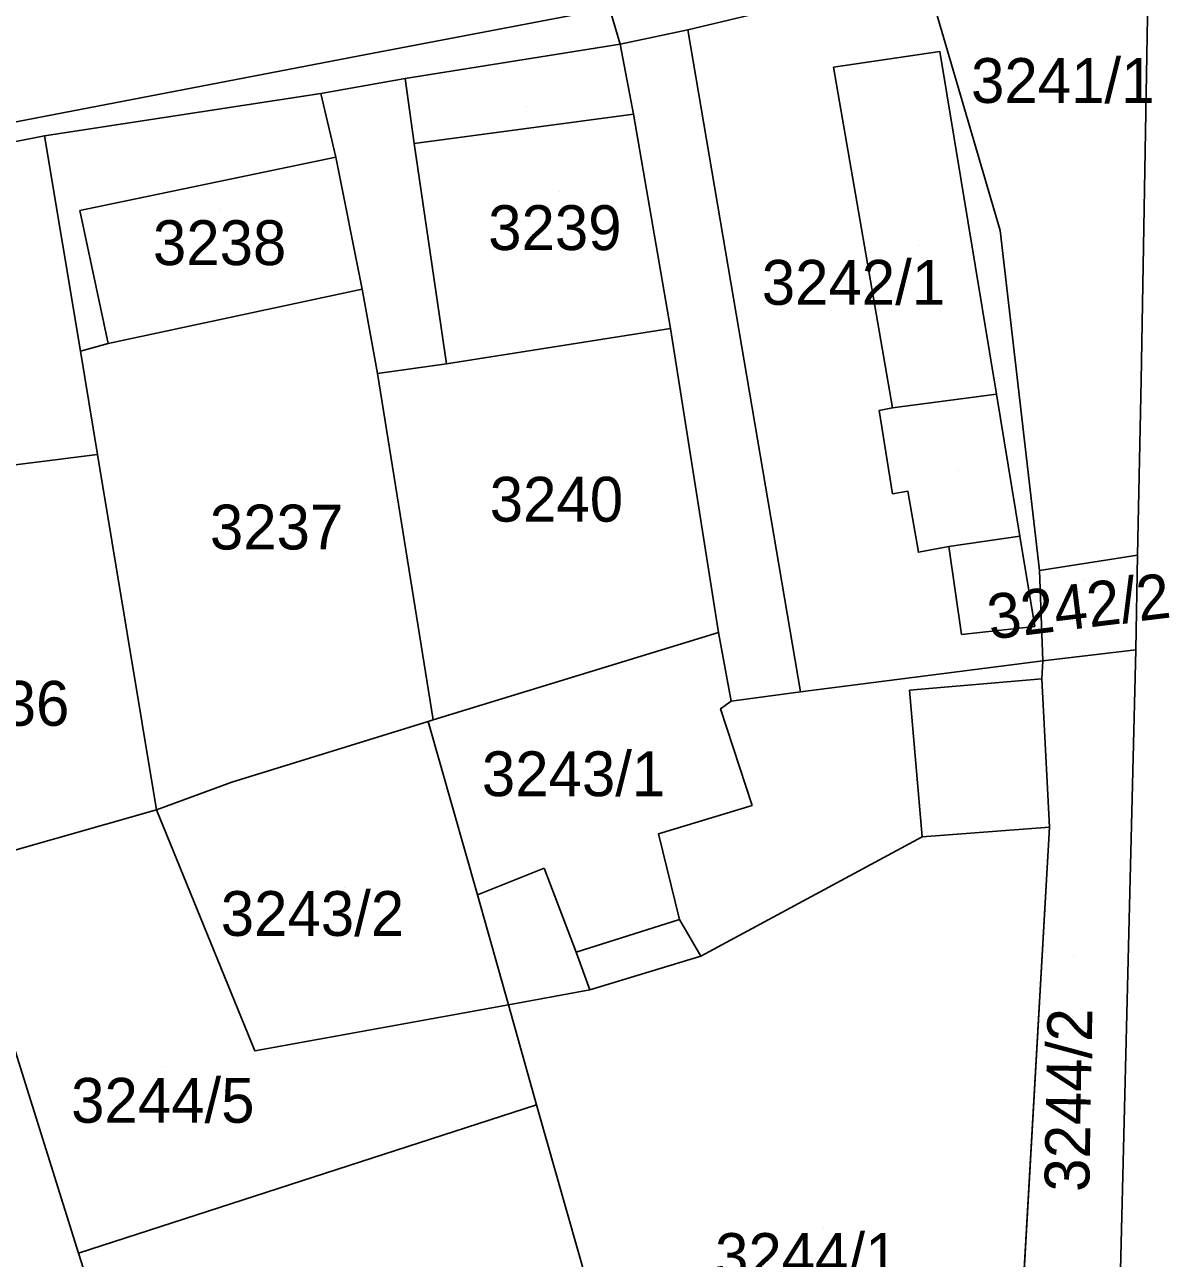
# Model space of a CAD drawing. Extents: x -262657 to -261595, y -1238015 to -1237156.
# Drawn here: x -261855.8 to -261804.7, y -1237748.7 to -1237693.7 of the extents above; entities that cross this region are included whole.
import ezdxf

# ---------------------------------------------------------------- set-up
doc = ezdxf.new("R2010")
doc.units = 0
for name, color, linetype in [('body_kn', 7, 'Continuous'), ('kladpar_druhypozemkov', 7, 'Continuous'), ('kladpar_hranice', 7, 'Continuous'), ('kladpar_parcelnecisla', 7, 'Continuous'), ('kladpar_plochy', 7, 'Continuous'), ('tarchy_linie', 7, 'Continuous'), ('zappar_hrandruhpozemk', 7, 'Continuous')]:
    doc.layers.add(name, color=color, linetype=linetype)

msp = doc.modelspace()

# ---------------------------------------------------------------- linework, layer by layer
at = {"layer": 'body_kn'}
for p, q in [((-261826.22, -1237693.91), (-261826.22, -1237693.91)), ((-261826.22, -1237693.91), (-261826.22, -1237693.91)), ((-261829.24, -1237694.55), (-261829.24, -1237694.55)), ((-261829.24, -1237694.55), (-261829.24, -1237694.55)), ((-261814.99, -1237694.87), (-261814.99, -1237694.87)), ((-261840.58, -1237695.01), (-261840.58, -1237695.01)), ((-261819.73, -1237695.57), (-261819.73, -1237695.57)), ((-261819.73, -1237695.57), (-261819.73, -1237695.57)), ((-261838.83, -1237696.08), (-261838.83, -1237696.08)), ((-261842.59, -1237696.75), (-261842.59, -1237696.75)), ((-261842.59, -1237696.75), (-261842.59, -1237696.75)), ((-261828.65, -1237697.67), (-261828.65, -1237697.67)), ((-261828.65, -1237697.67), (-261828.65, -1237697.67)), ((-261854.92, -1237698.64), (-261854.92, -1237698.64)), ((-261854.92, -1237698.64), (-261854.92, -1237698.64)), ((-261838.43, -1237698.98), (-261838.43, -1237698.98)), ((-261838.43, -1237698.98), (-261838.43, -1237698.98)), ((-261841.92, -1237699.59), (-261841.92, -1237699.59)), ((-261805.84, -1237700.16), (-261805.84, -1237700.16)), ((-261853.35, -1237701.96), (-261853.35, -1237701.96)), ((-261812.29, -1237702.86), (-261812.29, -1237702.86)), ((-261840.75, -1237705.47), (-261840.75, -1237705.47)), ((-261827, -1237707.23), (-261827, -1237707.23)), ((-261852.08, -1237707.9), (-261852.08, -1237707.9)), ((-261852.08, -1237707.9), (-261852.08, -1237707.9)), ((-261853.32, -1237708.24), (-261853.32, -1237708.24)), ((-261840.06, -1237709.24), (-261840.06, -1237709.24)), ((-261836.99, -1237708.8), (-261836.99, -1237708.8)), ((-261806, -1237709.55), (-261806, -1237709.55)), ((-261812.46, -1237710.15), (-261812.46, -1237710.15)), ((-261817.69, -1237710.88), (-261817.69, -1237710.88)), ((-261817.09, -1237710.76), (-261817.09, -1237710.76)), ((-261817.09, -1237710.76), (-261817.09, -1237710.76)), ((-261852.56, -1237712.85), (-261852.56, -1237712.85)), ((-261817.09, -1237714.6), (-261817.09, -1237714.6)), ((-261816.41, -1237714.48), (-261816.41, -1237714.48)), ((-261814.58, -1237716.95), (-261814.58, -1237716.95)), ((-261814.58, -1237716.95), (-261814.58, -1237716.95)), ((-261811.41, -1237716.49), (-261811.41, -1237716.49)), ((-261815.94, -1237717.2), (-261815.94, -1237717.2)), ((-261806.16, -1237717.33), (-261806.16, -1237717.33)), ((-261810.54, -1237718.01), (-261810.54, -1237718.01)), ((-261824.85, -1237720.78), (-261824.85, -1237720.78)), ((-261810.75, -1237720.51), (-261810.75, -1237720.51)), ((-261814.01, -1237720.87), (-261814.01, -1237720.87)), ((-261806.24, -1237721.56), (-261806.24, -1237721.56)), ((-261810.39, -1237722.04), (-261810.39, -1237722.04)), ((-261810.39, -1237722.04), (-261810.39, -1237722.04)), ((-261810.43, -1237722.85), (-261810.43, -1237722.85)), ((-261810.43, -1237722.85), (-261810.43, -1237722.85)), ((-261821.2, -1237723.42), (-261821.2, -1237723.42)), ((-261816.34, -1237723.35), (-261816.34, -1237723.35)), ((-261824.29, -1237723.84), (-261824.29, -1237723.84)), ((-261824.76, -1237724.18), (-261824.76, -1237724.18)), ((-261837.8, -1237724.75), (-261837.8, -1237724.75)), ((-261837.8, -1237724.75), (-261837.8, -1237724.75)), ((-261837.58, -1237724.68), (-261837.58, -1237724.68)), ((-261837.58, -1237724.68), (-261837.58, -1237724.68)), ((-261846.57, -1237727.46), (-261846.57, -1237727.46)), ((-261823.36, -1237728.5), (-261823.36, -1237728.5)), ((-261849.93, -1237728.69), (-261849.93, -1237728.69)), ((-261849.93, -1237728.69), (-261849.93, -1237728.69)), ((-261810.09, -1237729.46), (-261810.09, -1237729.46)), ((-261810.09, -1237729.46), (-261810.09, -1237729.46)), ((-261827.54, -1237729.76), (-261827.54, -1237729.76)), ((-261815.77, -1237729.89), (-261815.77, -1237729.89)), ((-261832.64, -1237731.29), (-261832.64, -1237731.29)), ((-261835.61, -1237732.48), (-261835.61, -1237732.48)), ((-261835.61, -1237732.48), (-261835.61, -1237732.48)), ((-261826.6, -1237733.58), (-261826.6, -1237733.58)), ((-261831.21, -1237735.03), (-261831.21, -1237735.03)), ((-261825.65, -1237735.22), (-261825.65, -1237735.22)), ((-261830.6, -1237736.72), (-261830.6, -1237736.72)), ((-261834.22, -1237737.38), (-261834.22, -1237737.38)), ((-261845.54, -1237739.43), (-261845.54, -1237739.43)), ((-261832.97, -1237741.84), (-261832.97, -1237741.84)), ((-261853.4, -1237748.46), (-261853.4, -1237748.46))]:
    msp.add_line(p, q, dxfattribs=at)
at = {"layer": 'kladpar_druhypozemkov'}
for p, q in [((-261809.96, -1237695.1), (-261809.96, -1237695.1)), ((-261833.43, -1237697.34), (-261833.43, -1237697.34)), ((-261831.97, -1237701.13), (-261831.97, -1237701.13)), ((-261847.09, -1237701.92), (-261847.09, -1237701.92)), ((-261815.9, -1237703.54), (-261815.9, -1237703.54)), ((-261814.16, -1237713.57), (-261814.16, -1237713.57)), ((-261831.97, -1237714.18), (-261831.97, -1237714.18)), ((-261844.26, -1237715.4), (-261844.26, -1237715.4)), ((-261808.53, -1237718.42), (-261808.53, -1237718.42)), ((-261830.66, -1237726.42), (-261830.66, -1237726.42)), ((-261841.56, -1237732.14), (-261841.56, -1237732.14)), ((-261809.02, -1237735.2), (-261809.02, -1237735.2)), ((-261849.54, -1237740.13), (-261849.54, -1237740.13)), ((-261820.16, -1237747.37), (-261820.16, -1237747.37))]:
    msp.add_line(p, q, dxfattribs=at)
at = {"layer": 'kladpar_hranice'}
for p, q in [((-261811.6, -1237755.76), (-261810.09, -1237729.46)), ((-261810.09, -1237729.46), (-261811.6, -1237755.76))]:
    msp.add_line(p, q, dxfattribs=at)
for points in [[(-261806.69, -1237689.75), (-261806.16, -1237692.56), (-261805.71, -1237692.47), (-261805.84, -1237700.16), (-261806, -1237709.55), (-261806.16, -1237717.33), (-261810.54, -1237718.01), (-261812.29, -1237702.86), (-261815.65, -1237691.39), (-261812.47, -1237690.82), (-261810.26, -1237690.45), (-261806.69, -1237689.75)], [(-261815.65, -1237691.39), (-261826.22, -1237693.91), (-261829.24, -1237694.55), (-261838.83, -1237696.08), (-261842.59, -1237696.75), (-261854.92, -1237698.64), (-261868.9, -1237701.4), (-261879, -1237704.16), (-261885.26, -1237705.39), (-261886.66, -1237705.67), (-261889.62, -1237706.2), (-261900.57, -1237708.21)], [(-261829.24, -1237694.55), (-261826.22, -1237693.91), (-261815.65, -1237691.39), (-261812.29, -1237702.86), (-261810.54, -1237718.01), (-261810.39, -1237722.04), (-261821.2, -1237723.42), (-261824.29, -1237723.84), (-261824.85, -1237720.78), (-261827, -1237707.23), (-261828.65, -1237697.67), (-261829.24, -1237694.55)], [(-261842.59, -1237696.75), (-261838.83, -1237696.08), (-261829.24, -1237694.55), (-261828.65, -1237697.67), (-261827, -1237707.23), (-261836.99, -1237708.8), (-261840.06, -1237709.24), (-261840.75, -1237705.47), (-261841.92, -1237699.59), (-261842.59, -1237696.75)], [(-261854.92, -1237698.64), (-261842.59, -1237696.75), (-261841.92, -1237699.59), (-261840.75, -1237705.47), (-261852.08, -1237707.9), (-261853.32, -1237708.24), (-261854.92, -1237698.64)], [(-261868.9, -1237701.4), (-261854.92, -1237698.64), (-261853.32, -1237708.24), (-261852.56, -1237712.85), (-261864.53, -1237714.35), (-261868.9, -1237701.4)], [(-261837.58, -1237724.68), (-261837.8, -1237724.75), (-261846.57, -1237727.46), (-261849.93, -1237728.69), (-261852.56, -1237712.85), (-261853.32, -1237708.24), (-261852.08, -1237707.9), (-261840.75, -1237705.47), (-261840.06, -1237709.24), (-261837.58, -1237724.68)], [(-261837.58, -1237724.68), (-261840.06, -1237709.24), (-261836.99, -1237708.8), (-261827, -1237707.23), (-261824.85, -1237720.78), (-261837.58, -1237724.68)], [(-261858.82, -1237731.22), (-261861.09, -1237724.45), (-261861.86, -1237722.15), (-261862.57, -1237720.05), (-261864.53, -1237714.35), (-261852.56, -1237712.85), (-261849.93, -1237728.69), (-261858.82, -1237731.22)], [(-261810.39, -1237722.04), (-261810.54, -1237718.01), (-261806.16, -1237717.33), (-261806.24, -1237721.56), (-261810.39, -1237722.04)], [(-261837.8, -1237724.75), (-261837.58, -1237724.68), (-261824.85, -1237720.78), (-261824.29, -1237723.84), (-261821.2, -1237723.42), (-261810.39, -1237722.04), (-261810.43, -1237722.85), (-261810.09, -1237729.46), (-261815.77, -1237729.89), (-261825.65, -1237735.22), (-261830.6, -1237736.72), (-261834.22, -1237737.38), (-261835.61, -1237732.48), (-261837.8, -1237724.75)], [(-261810.39, -1237722.04), (-261806.24, -1237721.56), (-261807.05, -1237754.01), (-261811.6, -1237755.76)], [(-261810.09, -1237729.46), (-261810.43, -1237722.85), (-261810.39, -1237722.04)], [(-261849.93, -1237728.69), (-261846.57, -1237727.46), (-261837.8, -1237724.75), (-261835.61, -1237732.48), (-261834.22, -1237737.38), (-261845.54, -1237739.43), (-261849.93, -1237728.69)], [(-261849.93, -1237728.69), (-261845.54, -1237739.43), (-261834.22, -1237737.38), (-261832.97, -1237741.84), (-261853.4, -1237748.46), (-261858.82, -1237731.22), (-261849.93, -1237728.69)], [(-261811.6, -1237755.76), (-261860.68, -1237774.55), (-261869.5, -1237752.69), (-261870.26, -1237752.98), (-261874.12, -1237742.17), (-261876.61, -1237737.16), (-261872.44, -1237735.73), (-261868.9, -1237734.59), (-261864.8, -1237732.66), (-261858.82, -1237731.22), (-261853.4, -1237748.46), (-261848.36, -1237764.27), (-261828.48, -1237757.63), (-261832.97, -1237741.84), (-261834.22, -1237737.38), (-261830.6, -1237736.72), (-261825.65, -1237735.22), (-261815.77, -1237729.89), (-261810.09, -1237729.46)], [(-261848.36, -1237764.27), (-261853.4, -1237748.46), (-261832.97, -1237741.84), (-261828.48, -1237757.63), (-261848.36, -1237764.27)]]:
    msp.add_lwpolyline(points, dxfattribs=at)
at = {"layer": 'kladpar_plochy'}
for points in [[(-261806.69, -1237689.75), (-261806.16, -1237692.56), (-261805.71, -1237692.47), (-261805.84, -1237700.16), (-261806, -1237709.55), (-261806.16, -1237717.33), (-261810.54, -1237718.01), (-261812.29, -1237702.86), (-261815.65, -1237691.39), (-261812.47, -1237690.82), (-261810.26, -1237690.45)], [(-261829.24, -1237694.55), (-261826.22, -1237693.91), (-261815.65, -1237691.39), (-261812.29, -1237702.86), (-261810.54, -1237718.01), (-261810.39, -1237722.04), (-261821.2, -1237723.42), (-261824.29, -1237723.84), (-261824.85, -1237720.78), (-261827, -1237707.23), (-261828.65, -1237697.67)], [(-261842.59, -1237696.75), (-261838.83, -1237696.08), (-261829.24, -1237694.55), (-261828.65, -1237697.67), (-261827, -1237707.23), (-261836.99, -1237708.8), (-261840.06, -1237709.24), (-261840.75, -1237705.47), (-261841.92, -1237699.59)], [(-261854.92, -1237698.64), (-261842.59, -1237696.75), (-261841.92, -1237699.59), (-261840.75, -1237705.47), (-261852.08, -1237707.9), (-261853.32, -1237708.24)], [(-261868.9, -1237701.4), (-261854.92, -1237698.64), (-261853.32, -1237708.24), (-261852.56, -1237712.85), (-261864.53, -1237714.35)], [(-261837.58, -1237724.68), (-261837.8, -1237724.75), (-261846.57, -1237727.46), (-261849.93, -1237728.69), (-261852.56, -1237712.85), (-261853.32, -1237708.24), (-261852.08, -1237707.9), (-261840.75, -1237705.47), (-261840.06, -1237709.24)], [(-261837.58, -1237724.68), (-261840.06, -1237709.24), (-261836.99, -1237708.8), (-261827, -1237707.23), (-261824.85, -1237720.78)], [(-261858.82, -1237731.22), (-261861.09, -1237724.45), (-261861.86, -1237722.15), (-261862.57, -1237720.05), (-261864.53, -1237714.35), (-261852.56, -1237712.85), (-261849.93, -1237728.69)], [(-261810.39, -1237722.04), (-261810.54, -1237718.01), (-261806.16, -1237717.33), (-261806.24, -1237721.56)], [(-261837.8, -1237724.75), (-261837.58, -1237724.68), (-261824.85, -1237720.78), (-261824.29, -1237723.84), (-261821.2, -1237723.42), (-261810.39, -1237722.04), (-261810.43, -1237722.85), (-261810.09, -1237729.46), (-261815.77, -1237729.89), (-261825.65, -1237735.22), (-261830.6, -1237736.72), (-261834.22, -1237737.38), (-261835.61, -1237732.48)], [(-261810.39, -1237722.04), (-261806.24, -1237721.56), (-261807.05, -1237754.01), (-261811.6, -1237755.76), (-261810.09, -1237729.46), (-261810.43, -1237722.85)], [(-261849.93, -1237728.69), (-261846.57, -1237727.46), (-261837.8, -1237724.75), (-261835.61, -1237732.48), (-261834.22, -1237737.38), (-261845.54, -1237739.43)], [(-261849.93, -1237728.69), (-261845.54, -1237739.43), (-261834.22, -1237737.38), (-261832.97, -1237741.84), (-261853.4, -1237748.46), (-261858.82, -1237731.22)], [(-261810.09, -1237729.46), (-261811.6, -1237755.76), (-261860.68, -1237774.55), (-261869.5, -1237752.69), (-261870.26, -1237752.98), (-261874.12, -1237742.17), (-261876.61, -1237737.16), (-261872.44, -1237735.73), (-261868.9, -1237734.59), (-261864.8, -1237732.66), (-261858.82, -1237731.22), (-261853.4, -1237748.46), (-261848.36, -1237764.27), (-261828.48, -1237757.63), (-261832.97, -1237741.84), (-261834.22, -1237737.38), (-261830.6, -1237736.72), (-261825.65, -1237735.22), (-261815.77, -1237729.89)], [(-261848.36, -1237764.27), (-261853.4, -1237748.46), (-261832.97, -1237741.84), (-261828.48, -1237757.63)]]:
    msp.add_lwpolyline(points, close=True, dxfattribs=at)
msp.add_lwpolyline([(-261815.65, -1237691.39), (-261826.22, -1237693.91), (-261829.24, -1237694.55), (-261838.83, -1237696.08), (-261842.59, -1237696.75), (-261854.92, -1237698.64), (-261868.9, -1237701.4), (-261879, -1237704.16), (-261885.26, -1237705.39), (-261886.66, -1237705.67), (-261889.62, -1237706.2), (-261900.57, -1237708.21)], dxfattribs=at)
at = {"layer": 'tarchy_linie'}
msp.add_lwpolyline([(-261829.24, -1237694.55), (-261826.22, -1237693.91), (-261821.2, -1237723.42), (-261824.29, -1237723.84), (-261824.85, -1237720.78), (-261827, -1237707.23), (-261828.65, -1237697.67), (-261829.24, -1237694.55)], dxfattribs=at)
at = {"layer": 'zappar_hrandruhpozemk'}
for p, q in [((-261826.22, -1237693.91), (-261821.2, -1237723.42)), ((-261838.43, -1237698.98), (-261838.83, -1237696.08)), ((-261853.35, -1237701.96), (-261841.92, -1237699.59)), ((-261852.08, -1237707.9), (-261853.35, -1237701.96)), ((-261817.09, -1237710.76), (-261812.46, -1237710.15)), ((-261817.09, -1237714.6), (-261817.69, -1237710.88)), ((-261814.58, -1237716.95), (-261811.41, -1237716.49)), ((-261810.75, -1237720.51), (-261814.01, -1237720.87)), ((-261810.43, -1237722.85), (-261816.34, -1237723.35)), ((-261816.34, -1237723.35), (-261815.77, -1237729.89)), ((-261827.54, -1237729.76), (-261823.36, -1237728.5)), ((-261826.6, -1237733.58), (-261827.54, -1237729.76)), ((-261835.61, -1237732.48), (-261832.64, -1237731.29)), ((-261832.64, -1237731.29), (-261831.21, -1237735.03)), ((-261831.21, -1237735.03), (-261826.6, -1237733.58)), ((-261826.6, -1237733.58), (-261825.65, -1237735.22)), ((-261831.21, -1237735.03), (-261830.6, -1237736.72))]:
    msp.add_line(p, q, dxfattribs=at)
for points in [[(-261869.66, -1237700.6), (-261840.58, -1237695.01), (-261829.72, -1237692.94), (-261829.24, -1237694.55)], [(-261819.73, -1237695.57), (-261814.99, -1237694.87), (-261812.46, -1237710.15), (-261811.41, -1237716.49), (-261810.75, -1237720.51)], [(-261817.69, -1237710.88), (-261817.09, -1237710.76), (-261819.73, -1237695.57)], [(-261828.65, -1237697.67), (-261838.43, -1237698.98), (-261836.99, -1237708.8)], [(-261814.01, -1237720.87), (-261814.58, -1237716.95), (-261815.94, -1237717.2), (-261816.41, -1237714.48), (-261817.09, -1237714.6)], [(-261823.36, -1237728.5), (-261824.76, -1237724.18), (-261824.29, -1237723.84)]]:
    msp.add_lwpolyline(points, dxfattribs=at)

# ---------------------------------------------------------------- texts
at = {"layer": 'kladpar_parcelnecisla'}
for s, p in [('3241/1', (-261813.59, -1237697.17)), ('3239', (-261835.131, -1237703.73)), ('3238', (-261850.085, -1237704.4)), ('3242/1', (-261822.926, -1237706.17)), ('3240', (-261835.06, -1237715.84)), ('3237', (-261847.544, -1237717.08)), ('3236', (-261859.761, -1237724.94)), ('3243/1', (-261835.412, -1237728.08)), ('3243/2', (-261847.058, -1237734.31)), ('3244/5', (-261853.734, -1237742.64)), ('3244/1', (-261825.01, -1237749.56))]:
    msp.add_text(s, height=2, dxfattribs=at).set_placement(p)
for s, rotation, p in [('3242/2', 7, (-261812.732, -1237721.098)), ('3244/2', 89, (-261808.32, -1237745.732))]:
    msp.add_text(s, height=2, rotation=rotation, dxfattribs=at).set_placement(p)

doc.saveas('drawing.dxf')
